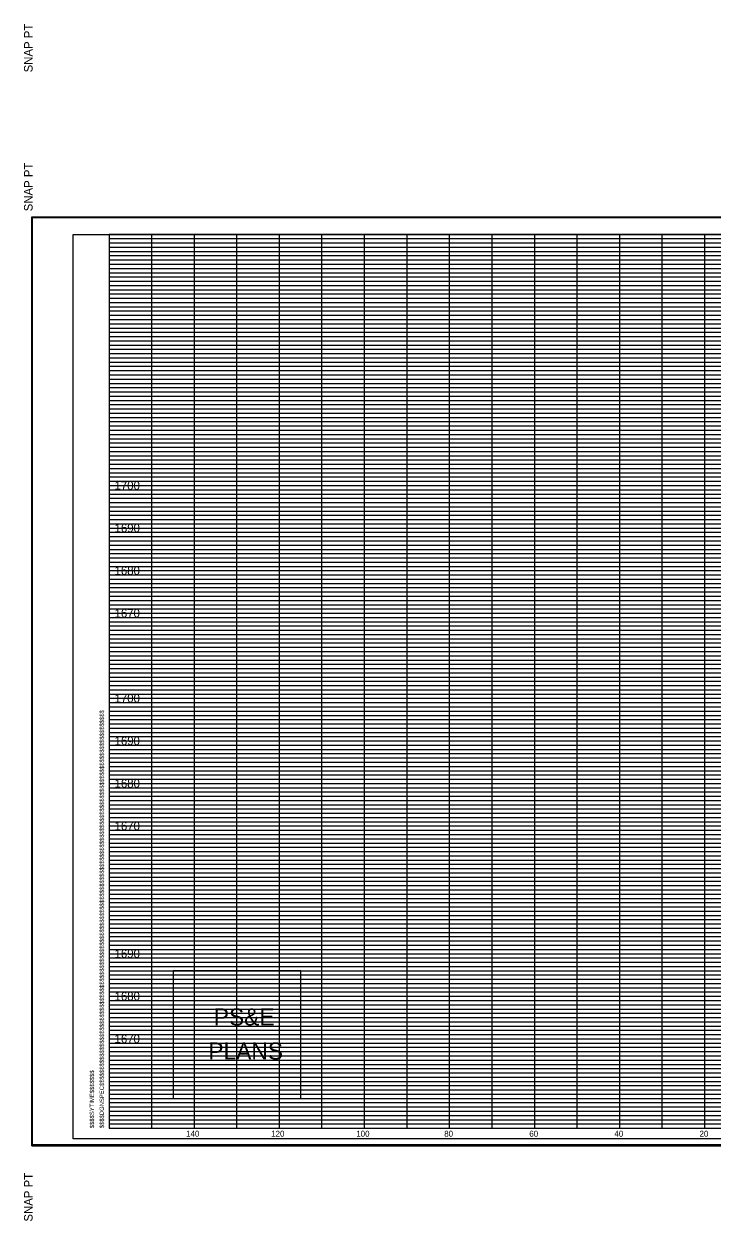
# Model space of a CAD drawing. Extents: x 980 to 2228, y 978 to 2394.
# Drawn here: x 979.9 to 1141.7, y 978.2 to 1259.4 of the extents above; entities that cross this region are included whole.
import ezdxf

# ---------------------------------------------------------------- set-up
doc = ezdxf.new("R2010")
doc.units = 0
for name, color, linetype in [('DESIGN - SHEET - Corner Text', 7, 'Continuous'), ('DESIGN - SHEET - Light Grid', 7, 'Continuous'), ('DESIGN - SHEET - Linework', 7, 'Continuous'), ('DESIGN - SHEET - Plot Shape', 7, 'Continuous'), ('DESIGN - TYPICAL - Finished Grade and Subgrade', 7, 'Continuous')]:
    doc.layers.add(name, color=color, linetype=linetype)

# ---------------------------------------------------------------- blocks, each defined once
blk = doc.blocks.new('XSTSHT')
at = {"layer": 'DESIGN - SHEET - Light Grid'}
for p, q in [((0, 20.9), (8, 20.9)), ((8, 20.9), (16, 20.9)), ((0, 20.8), (8, 20.8)), ((0, 20.7), (8, 20.7)), ((0, 20.6), (8, 20.6)), ((8, 20.8), (16, 20.8)), ((8, 20.7), (16, 20.7)), ((8, 20.6), (16, 20.6)), ((0, 20.5), (8, 20.5)), ((0, 20.4), (8, 20.4)), ((0, 20.3), (8, 20.3)), ((8, 20.5), (16, 20.5)), ((8, 20.4), (16, 20.4)), ((8, 20.3), (16, 20.3)), ((0, 20.2), (8, 20.2)), ((0, 20.1), (8, 20.1)), ((8, 20.2), (16, 20.2)), ((8, 20.1), (16, 20.1)), ((0, 19.9), (8, 19.9)), ((0, 19.8), (8, 19.8)), ((0, 19.7), (8, 19.7)), ((8, 19.9), (16, 19.9)), ((8, 19.8), (16, 19.8)), ((8, 19.7), (16, 19.7)), ((0, 19.6), (8, 19.6)), ((0, 19.5), (8, 19.5)), ((8, 19.6), (16, 19.6)), ((8, 19.5), (16, 19.5)), ((0, 19.4), (8, 19.4)), ((0, 19.3), (8, 19.3)), ((0, 19.2), (8, 19.2)), ((8, 19.4), (16, 19.4)), ((8, 19.3), (16, 19.3)), ((8, 19.2), (16, 19.2)), ((0, 19.1), (8, 19.1)), ((0, 18.9), (8, 18.9)), ((8, 19.1), (16, 19.1)), ((8, 18.9), (16, 18.9)), ((0, 18.8), (8, 18.8)), ((0, 18.7), (8, 18.7)), ((0, 18.6), (8, 18.6)), ((8, 18.8), (16, 18.8)), ((8, 18.7), (16, 18.7)), ((8, 18.6), (16, 18.6)), ((0, 18.5), (8, 18.5)), ((0, 18.4), (8, 18.4)), ((0, 18.3), (8, 18.3)), ((8, 18.5), (16, 18.5)), ((8, 18.4), (16, 18.4)), ((8, 18.3), (16, 18.3)), ((0, 18.2), (8, 18.2)), ((0, 18.1), (8, 18.1)), ((8, 18.2), (16, 18.2)), ((8, 18.1), (16, 18.1)), ((0, 17.9), (8, 17.9)), ((0, 17.8), (8, 17.8)), ((8, 17.9), (16, 17.9)), ((8, 17.8), (16, 17.8)), ((0, 17.7), (8, 17.7)), ((0, 17.6), (8, 17.6)), ((0, 17.5), (8, 17.5)), ((8, 17.7), (16, 17.7)), ((8, 17.6), (16, 17.6)), ((8, 17.5), (16, 17.5)), ((0, 17.4), (8, 17.4)), ((0, 17.3), (8, 17.3)), ((0, 17.2), (8, 17.2)), ((8, 17.4), (16, 17.4)), ((8, 17.3), (16, 17.3)), ((8, 17.2), (16, 17.2)), ((0, 17.1), (8, 17.1)), ((0, 16.9), (8, 16.9)), ((8, 17.1), (16, 17.1)), ((8, 16.9), (16, 16.9)), ((0, 16.8), (8, 16.8)), ((0, 16.7), (8, 16.7)), ((0, 16.6), (8, 16.6)), ((8, 16.8), (16, 16.8)), ((8, 16.7), (16, 16.7)), ((8, 16.6), (16, 16.6)), ((0, 16.5), (8, 16.5)), ((0, 16.4), (8, 16.4)), ((8, 16.5), (16, 16.5)), ((8, 16.4), (16, 16.4)), ((0, 16.3), (8, 16.3)), ((0, 16.2), (8, 16.2)), ((0, 16.1), (8, 16.1)), ((8, 16.3), (16, 16.3)), ((8, 16.2), (16, 16.2)), ((8, 16.1), (16, 16.1)), ((0, 15.9), (8, 15.9)), ((0, 15.8), (8, 15.8)), ((8, 15.9), (16, 15.9)), ((8, 15.8), (16, 15.8)), ((0, 15.7), (8, 15.7)), ((0, 15.6), (8, 15.6)), ((0, 15.5), (8, 15.5)), ((8, 15.7), (16, 15.7)), ((8, 15.6), (16, 15.6)), ((8, 15.5), (16, 15.5)), ((0, 15.4), (8, 15.4)), ((0, 15.3), (8, 15.3)), ((0, 15.2), (8, 15.2)), ((8, 15.4), (16, 15.4)), ((8, 15.3), (16, 15.3)), ((8, 15.2), (16, 15.2)), ((0, 15.1), (8, 15.1)), ((8, 15.1), (16, 15.1)), ((0, 14.9), (8, 14.9)), ((0, 14.8), (8, 14.8)), ((0, 14.7), (8, 14.7)), ((8, 14.9), (16, 14.9)), ((8, 14.8), (16, 14.8)), ((8, 14.7), (16, 14.7)), ((0, 14.6), (8, 14.6)), ((0, 14.5), (8, 14.5)), ((0, 14.4), (8, 14.4)), ((8, 14.6), (16, 14.6)), ((8, 14.5), (16, 14.5)), ((8, 14.4), (16, 14.4)), ((0, 14.3), (8, 14.3)), ((0, 14.2), (8, 14.2)), ((0, 14.1), (8, 14.1)), ((8, 14.3), (16, 14.3)), ((8, 14.2), (16, 14.2)), ((8, 14.1), (16, 14.1)), ((0, 13.9), (8, 13.9)), ((0, 13.8), (8, 13.8)), ((8, 13.9), (16, 13.9)), ((8, 13.8), (16, 13.8)), ((0, 13.7), (8, 13.7)), ((0, 13.6), (8, 13.6)), ((8, 13.7), (16, 13.7)), ((8, 13.6), (16, 13.6)), ((0, 13.5), (8, 13.5)), ((0, 13.4), (8, 13.4)), ((0, 13.3), (8, 13.3)), ((8, 13.5), (16, 13.5)), ((8, 13.4), (16, 13.4)), ((8, 13.3), (16, 13.3)), ((0, 13.2), (8, 13.2)), ((0, 13.1), (8, 13.1)), ((8, 13.2), (16, 13.2)), ((8, 13.1), (16, 13.1)), ((0, 12.9), (8, 12.9)), ((0, 12.8), (8, 12.8)), ((0, 12.7), (8, 12.7)), ((8, 12.9), (16, 12.9)), ((8, 12.8), (16, 12.8)), ((8, 12.7), (16, 12.7)), ((0, 12.6), (8, 12.6)), ((0, 12.5), (8, 12.5)), ((0, 12.4), (8, 12.4)), ((8, 12.6), (16, 12.6)), ((8, 12.5), (16, 12.5)), ((8, 12.4), (16, 12.4)), ((0, 12.3), (8, 12.3)), ((0, 12.2), (8, 12.2)), ((0, 12.1), (8, 12.1)), ((8, 12.3), (16, 12.3)), ((8, 12.2), (16, 12.2)), ((8, 12.1), (16, 12.1)), ((0, 11.9), (8, 11.9)), ((8, 11.9), (16, 11.9)), ((0, 11.8), (8, 11.8)), ((0, 11.7), (8, 11.7)), ((0, 11.6), (8, 11.6)), ((8, 11.8), (16, 11.8)), ((8, 11.7), (16, 11.7)), ((8, 11.6), (16, 11.6)), ((0, 11.5), (8, 11.5)), ((0, 11.4), (8, 11.4)), ((0, 11.3), (8, 11.3)), ((8, 11.5), (16, 11.5)), ((8, 11.4), (16, 11.4)), ((8, 11.3), (16, 11.3)), ((0, 11.2), (8, 11.2)), ((0, 11.1), (8, 11.1)), ((8, 11.2), (16, 11.2)), ((8, 11.1), (16, 11.1)), ((0, 10.9), (8, 10.9)), ((0, 10.8), (8, 10.8)), ((0, 10.7), (8, 10.7)), ((8, 10.9), (16, 10.9)), ((8, 10.8), (16, 10.8)), ((8, 10.7), (16, 10.7)), ((0, 10.6), (8, 10.6)), ((0, 10.5), (8, 10.5)), ((8, 10.6), (16, 10.6)), ((8, 10.5), (16, 10.5)), ((0, 10.4), (8, 10.4)), ((0, 10.3), (8, 10.3)), ((0, 10.2), (8, 10.2)), ((8, 10.4), (16, 10.4)), ((8, 10.3), (16, 10.3)), ((8, 10.2), (16, 10.2)), ((0, 10.1), (8, 10.1)), ((0, 9.9), (8, 9.9)), ((8, 10.1), (16, 10.1)), ((8, 9.9), (16, 9.9)), ((0, 9.8), (8, 9.8)), ((0, 9.7), (8, 9.7)), ((0, 9.6), (8, 9.6)), ((8, 9.8), (16, 9.8)), ((8, 9.7), (16, 9.7)), ((8, 9.6), (16, 9.6)), ((0, 9.5), (8, 9.5)), ((0, 9.4), (8, 9.4)), ((0, 9.3), (8, 9.3)), ((8, 9.5), (16, 9.5)), ((8, 9.4), (16, 9.4)), ((8, 9.3), (16, 9.3)), ((0, 9.2), (8, 9.2)), ((0, 9.1), (8, 9.1)), ((8, 9.2), (16, 9.2)), ((8, 9.1), (16, 9.1)), ((0, 8.9), (8, 8.9)), ((0, 8.8), (8, 8.8)), ((8, 8.9), (16, 8.9)), ((8, 8.8), (16, 8.8)), ((0, 8.7), (8, 8.7)), ((0, 8.6), (8, 8.6)), ((0, 8.5), (8, 8.5)), ((8, 8.7), (16, 8.7)), ((8, 8.6), (16, 8.6)), ((8, 8.5), (16, 8.5)), ((0, 8.4), (8, 8.4)), ((0, 8.3), (8, 8.3)), ((0, 8.2), (8, 8.2)), ((8, 8.4), (16, 8.4)), ((8, 8.3), (16, 8.3)), ((8, 8.2), (16, 8.2)), ((0, 8.1), (8, 8.1)), ((0, 7.9), (8, 7.9)), ((8, 8.1), (16, 8.1)), ((8, 7.9), (16, 7.9)), ((0, 7.8), (8, 7.8)), ((0, 7.7), (8, 7.7)), ((0, 7.6), (8, 7.6)), ((8, 7.8), (16, 7.8)), ((8, 7.7), (16, 7.7)), ((8, 7.6), (16, 7.6)), ((0, 7.5), (8, 7.5)), ((0, 7.4), (8, 7.4)), ((8, 7.5), (16, 7.5)), ((8, 7.4), (16, 7.4)), ((0, 7.3), (8, 7.3)), ((0, 7.2), (8, 7.2)), ((0, 7.1), (8, 7.1)), ((8, 7.3), (16, 7.3)), ((8, 7.2), (16, 7.2)), ((8, 7.1), (16, 7.1)), ((0, 6.9), (8, 6.9)), ((0, 6.8), (8, 6.8)), ((8, 6.9), (16, 6.9)), ((8, 6.8), (16, 6.8)), ((0, 6.7), (8, 6.7)), ((0, 6.6), (8, 6.6)), ((0, 6.5), (8, 6.5)), ((8, 6.7), (16, 6.7)), ((8, 6.6), (16, 6.6)), ((8, 6.5), (16, 6.5)), ((0, 6.4), (8, 6.4)), ((0, 6.3), (8, 6.3)), ((0, 6.2), (8, 6.2)), ((8, 6.4), (16, 6.4)), ((8, 6.3), (16, 6.3)), ((8, 6.2), (16, 6.2)), ((0, 6.1), (8, 6.1)), ((8, 6.1), (16, 6.1)), ((0, 5.9), (8, 5.9)), ((0, 5.8), (8, 5.8)), ((0, 5.7), (8, 5.7)), ((8, 5.9), (16, 5.9)), ((8, 5.8), (16, 5.8)), ((8, 5.7), (16, 5.7)), ((0, 5.6), (8, 5.6)), ((0, 5.5), (8, 5.5)), ((0, 5.4), (8, 5.4)), ((8, 5.6), (16, 5.6)), ((8, 5.5), (16, 5.5)), ((8, 5.4), (16, 5.4)), ((0, 5.3), (8, 5.3)), ((0, 5.2), (8, 5.2)), ((0, 5.1), (8, 5.1)), ((8, 5.3), (16, 5.3)), ((8, 5.2), (16, 5.2)), ((8, 5.1), (16, 5.1)), ((0, 4.9), (8, 4.9)), ((0, 4.8), (8, 4.8)), ((8, 4.9), (16, 4.9)), ((8, 4.8), (16, 4.8)), ((0, 4.7), (8, 4.7)), ((0, 4.6), (8, 4.6)), ((8, 4.7), (16, 4.7)), ((8, 4.6), (16, 4.6)), ((0, 4.5), (8, 4.5)), ((0, 4.4), (8, 4.4)), ((0, 4.3), (8, 4.3)), ((8, 4.5), (16, 4.5)), ((8, 4.4), (16, 4.4)), ((8, 4.3), (16, 4.3)), ((0, 4.2), (8, 4.2)), ((0, 4.1), (8, 4.1)), ((8, 4.2), (16, 4.2)), ((8, 4.1), (16, 4.1)), ((0, 3.9), (8, 3.9)), ((0, 3.8), (8, 3.8)), ((0, 3.7), (8, 3.7)), ((8, 3.9), (16, 3.9)), ((8, 3.8), (16, 3.8)), ((8, 3.7), (16, 3.7)), ((0, 3.6), (8, 3.6)), ((0, 3.5), (8, 3.5)), ((0, 3.4), (8, 3.4)), ((8, 3.6), (16, 3.6)), ((8, 3.5), (16, 3.5)), ((8, 3.4), (16, 3.4)), ((0, 3.3), (8, 3.3)), ((0, 3.2), (8, 3.2)), ((0, 3.1), (8, 3.1)), ((8, 3.3), (16, 3.3)), ((8, 3.2), (16, 3.2)), ((8, 3.1), (16, 3.1)), ((0, 2.9), (8, 2.9)), ((8, 2.9), (16, 2.9)), ((0, 2.8), (8, 2.8)), ((0, 2.7), (8, 2.7)), ((0, 2.6), (8, 2.6)), ((8, 2.8), (16, 2.8)), ((8, 2.7), (16, 2.7)), ((8, 2.6), (16, 2.6)), ((0, 2.5), (8, 2.5)), ((0, 2.4), (8, 2.4)), ((0, 2.3), (8, 2.3)), ((8, 2.5), (16, 2.5)), ((8, 2.4), (16, 2.4)), ((8, 2.3), (16, 2.3)), ((0, 2.2), (8, 2.2)), ((0, 2.1), (8, 2.1)), ((8, 2.2), (16, 2.2)), ((8, 2.1), (16, 2.1)), ((0, 1.9), (8, 1.9)), ((0, 1.8), (8, 1.8)), ((0, 1.7), (8, 1.7)), ((8, 1.9), (16, 1.9)), ((8, 1.8), (16, 1.8)), ((8, 1.7), (16, 1.7)), ((0, 1.6), (8, 1.6)), ((0, 1.5), (8, 1.5)), ((8, 1.6), (16, 1.6)), ((8, 1.5), (16, 1.5)), ((0, 1.4), (8, 1.4)), ((0, 1.3), (8, 1.3)), ((0, 1.2), (8, 1.2)), ((8, 1.4), (16, 1.4)), ((8, 1.3), (16, 1.3)), ((8, 1.2), (16, 1.2)), ((0, 1.1), (8, 1.1)), ((0, 0.9), (8, 0.9)), ((8, 1.1), (16, 1.1)), ((8, 0.9), (16, 0.9)), ((0, 0.8), (8, 0.8)), ((0, 0.7), (8, 0.7)), ((0, 0.6), (8, 0.6)), ((8, 0.8), (16, 0.8)), ((8, 0.7), (16, 0.7)), ((8, 0.6), (16, 0.6)), ((0, 0.5), (8, 0.5)), ((0, 0.4), (8, 0.4)), ((0, 0.3), (8, 0.3)), ((8, 0.5), (16, 0.5)), ((8, 0.4), (16, 0.4)), ((8, 0.3), (16, 0.3)), ((0, 0.2), (8, 0.2)), ((0, 0.1), (8, 0.1)), ((8, 0.2), (16, 0.2)), ((8, 0.1), (16, 0.1))]:
    blk.add_line(p, q, dxfattribs=at)
at = {"layer": 'DESIGN - SHEET - Linework'}
for p, q in [((-1.823, -0.414), (-1.823, 21.414)), ((-1.823, 21.414), (32.217, 21.414)), ((1, 0), (1, 21)), ((2, 0), (2, 21)), ((3, 0), (3, 21)), ((4, 0), (4, 21)), ((5, 0), (5, 21)), ((6, 0), (6, 21)), ((7, 0), (7, 21)), ((8, 0), (8, 21)), ((9, 0), (9, 21)), ((10, 0), (10, 21)), ((11, 0), (11, 21)), ((12, 0), (12, 21)), ((13, 0), (13, 21)), ((14, 0), (14, 21)), ((0, 20), (28, 20)), ((0, 19), (32, 19)), ((0, 18), (32, 18)), ((0, 17), (32, 17)), ((0, 16), (32, 16)), ((0, 15), (32, 15)), ((0, 14), (32, 14)), ((0, 13), (32, 13)), ((0, 12), (32, 12)), ((0, 11), (32, 11)), ((0, 10), (32, 10)), ((0, 9), (32, 9)), ((0, 8), (32, 8)), ((0, 7), (32, 7)), ((0, 6), (32, 6)), ((0, 5), (32, 5)), ((0, 4), (32, 4)), ((0, 3), (32, 3)), ((0, 2), (32, 2)), ((0, 1), (32, 1)), ((-1.823, -0.414), (32.217, -0.414))]:
    blk.add_line(p, q, dxfattribs=at)
blk.add_lwpolyline([(0, 21), (0, 0), (32, 0), (32, 21), (0, 21)], dxfattribs=at)
at = {"layer": 'DESIGN - SHEET - Plot Shape'}
for points in [[(-1.803, 21.394), (32.197, 21.394), (32.197, -0.394), (-1.803, -0.394)], [(-0.85, 21), (32, 21), (32, -0.25), (-0.85, -0.25)]]:
    blk.add_lwpolyline(points, close=True, dxfattribs=at)
at = {"layer": 'DESIGN - SHEET - Corner Text'}
for s, height, p in [('  SNAP PT', 0.2, (-1.803, 21.394)), ('$$$$DGNSPEC$$$$$$$$$$$$$$$$$$$$$$$$$$$$$$$$$$$$$$$$$$$$$$$$$$$$$$$$$$$$$$$$$$$$$$$$$$$$$$$$$$$$$$$$$$$$$$$$$$$$$$$$$$$$$$$$$$$', 0.100002, (-0.126, 0)), ('$$$$SYTIME$$$$$$$', 0.1, (-0.358, 0)), ('SNAP PT  ', 0.2, (-1.803, -2.194))]:
    blk.add_text(s, height=height, rotation=90, dxfattribs=at).set_placement(p)

msp = doc.modelspace()

# ---------------------------------------------------------------- linework, layer by layer
at = {"layer": 'DESIGN - SHEET - Corner Text'}
msp.add_lwpolyline([(1015.06, 1036.97), (1015.06, 1006.97), (1045.06, 1006.97), (1045.06, 1036.97)], close=True, dxfattribs=at)
at = {"layer": 'DESIGN - SHEET - Plot Shape'}
msp.add_lwpolyline([(991.5, 1210), (1320, 1210), (1320, 997.5), (991.5, 997.5)], close=True, dxfattribs=at)

# ---------------------------------------------------------------- block references
at = {"layer": 'DESIGN - TYPICAL - Finished Grade and Subgrade', "xscale": 10, "yscale": 10}
for p in [(1000, 1270), (1000, 1000)]:
    msp.add_blockref('XSTSHT', p, dxfattribs=at)

# ---------------------------------------------------------------- texts
at = {"layer": 'DESIGN - SHEET - Corner Text'}
for s, height, p in [('1700', 2, (1001.25, 1150)), ('1690', 2, (1001.25, 1140)), ('1680', 2, (1001.25, 1130)), ('1670', 2, (1001.25, 1120)), ('1700', 2, (1001.25, 1100)), ('1690', 2, (1001.25, 1090)), ('1680', 2, (1001.25, 1080)), ('1670', 2, (1001.25, 1070)), ('1690', 2, (1001.25, 1040)), ('1680', 2, (1001.25, 1030)), ('PS&E', 4, (1024.58, 1024.14)), ('1670', 2, (1001.25, 1020)), ('PLANS', 4, (1023.3, 1016.14)), ('140', 1.4, (1018.06, 998)), ('120', 1.4, (1038.06, 998)), ('100', 1.4, (1058.06, 998)), ('80', 1.4, (1078.74, 998)), ('60', 1.4, (1098.74, 998)), ('40', 1.4, (1118.74, 998)), ('20', 1.4, (1138.74, 998))]:
    msp.add_text(s, height=height, dxfattribs=at).set_placement(p)

doc.saveas('drawing.dxf')
